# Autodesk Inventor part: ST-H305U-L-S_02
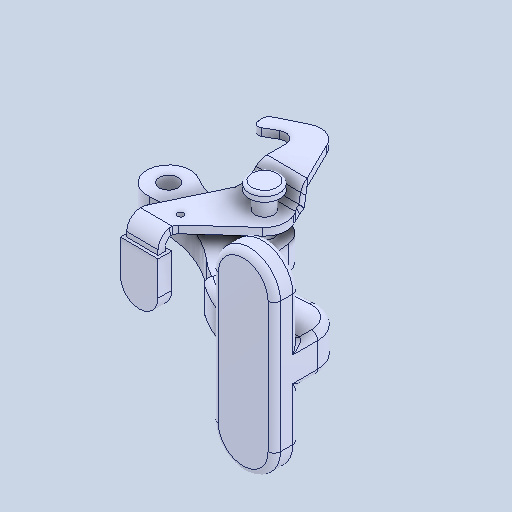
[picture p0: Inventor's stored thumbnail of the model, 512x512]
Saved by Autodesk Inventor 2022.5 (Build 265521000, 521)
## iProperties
Created: 2024-07
Part Number: ST-H305U-L-S_02
Material: 一般
Document SubType Name: Modeling
Designer: ImaoCorp
Density: 1 g/cm^3
Appearance: 既定
Author: ImaoCorp
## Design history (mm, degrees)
feature "ST-H305U-L-S_02"
node "ソリッド1"
